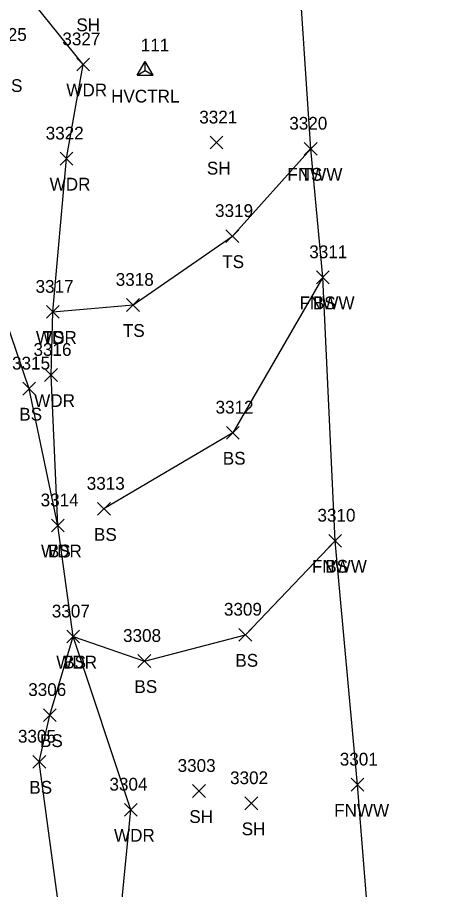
# Model space of a CAD drawing. Extents: x 1650221 to 1650634, y 244606 to 249996.
# Drawn here: x 1650457.2 to 1650522.4, y 246112 to 246248.6 of the extents above; entities that cross this region are included whole.
import ezdxf

# ---------------------------------------------------------------- set-up
doc = ezdxf.new("R2010")
doc.units = 0
for name, color, linetype in [('C_A', 7, 'Continuous'), ('C_I', 7, 'Continuous'), ('CPSM', 7, 'Continuous'), ('L_A', 7, 'Continuous'), ('L_I', 7, 'Continuous'), ('L_TIC', 7, 'Continuous'), ('LAWA', 7, 'Continuous'), ('LELB', 7, 'Continuous'), ('LFNC', 7, 'Continuous'), ('LSOGP', 7, 'Continuous')]:
    doc.layers.add(name, color=color, linetype=linetype)

msp = doc.modelspace()

# ---------------------------------------------------------------- linework, layer by layer
at = {"layer": 'CPSM'}
for p, q in [((1650475.88, 246239.57), (1650477.13, 246241.74)), ((1650478.38, 246239.57), (1650477.13, 246241.74)), ((1650477.13, 246240.29), (1650477.13, 246241.74)), ((1650475.88, 246239.57), (1650477.13, 246240.29)), ((1650477.13, 246240.29), (1650477.13, 246240.29)), ((1650477.13, 246240.29), (1650478.38, 246239.57)), ((1650475.88, 246239.57), (1650478.38, 246239.57))]:
    msp.add_line(p, q, dxfattribs=at)
at = {"layer": 'L_TIC'}
for points in [[(1650466.45, 246240.25), (1650468.45, 246242.25)], [(1650468.45, 246240.25), (1650466.45, 246242.25)], [(1650487.32, 246228.01), (1650489.32, 246230.01)], [(1650489.32, 246228.01), (1650487.32, 246230.01)], [(1650502.06, 246227.04), (1650504.06, 246229.04)], [(1650504.06, 246227.04), (1650502.06, 246229.04)], [(1650502.06, 246227.04), (1650504.06, 246229.04)], [(1650504.06, 246227.04), (1650502.06, 246229.04)], [(1650463.84, 246225.5), (1650465.84, 246227.5)], [(1650465.84, 246225.5), (1650463.84, 246227.5)], [(1650489.8, 246213.36), (1650491.8, 246215.36)], [(1650491.8, 246213.36), (1650489.8, 246215.36)], [(1650503.96, 246206.91), (1650505.96, 246208.91)], [(1650505.96, 246206.91), (1650503.96, 246208.91)], [(1650503.96, 246206.91), (1650505.96, 246208.91)], [(1650505.96, 246206.91), (1650503.96, 246208.91)], [(1650461.69, 246201.49), (1650463.69, 246203.49)], [(1650463.69, 246201.49), (1650461.69, 246203.49)], [(1650461.69, 246201.49), (1650463.69, 246203.49)], [(1650463.69, 246201.49), (1650461.69, 246203.49)], [(1650474.25, 246202.58), (1650476.25, 246204.58)], [(1650476.25, 246202.58), (1650474.25, 246204.58)], [(1650461.42, 246191.61), (1650463.42, 246193.61)], [(1650463.42, 246191.61), (1650461.42, 246193.61)], [(1650458.01, 246189.47), (1650460.01, 246191.47)], [(1650460.01, 246189.47), (1650458.01, 246191.47)], [(1650489.86, 246182.57), (1650491.86, 246184.57)], [(1650491.86, 246182.57), (1650489.86, 246184.57)], [(1650469.7, 246170.64), (1650471.7, 246172.64)], [(1650471.7, 246170.64), (1650469.7, 246172.64)], [(1650462.49, 246168.04), (1650464.49, 246170.04)], [(1650464.49, 246168.04), (1650462.49, 246170.04)], [(1650462.49, 246168.04), (1650464.49, 246170.04)], [(1650464.49, 246168.04), (1650462.49, 246170.04)], [(1650505.9, 246165.65), (1650507.9, 246167.65)], [(1650507.9, 246165.65), (1650505.9, 246167.65)], [(1650505.9, 246165.65), (1650507.9, 246167.65)], [(1650507.9, 246165.65), (1650505.9, 246167.65)], [(1650491.83, 246150.92), (1650493.83, 246152.92)], [(1650493.83, 246150.92), (1650491.83, 246152.92)], [(1650464.87, 246150.64), (1650466.87, 246152.64)], [(1650466.87, 246150.64), (1650464.87, 246152.64)], [(1650464.87, 246150.64), (1650466.87, 246152.64)], [(1650466.87, 246150.64), (1650464.87, 246152.64)], [(1650476.03, 246146.81), (1650478.03, 246148.81)], [(1650478.03, 246146.81), (1650476.03, 246148.81)], [(1650461.24, 246138.34), (1650463.24, 246140.34)], [(1650463.24, 246138.34), (1650461.24, 246140.34)], [(1650459.58, 246131.03), (1650461.58, 246133.03)], [(1650461.58, 246131.03), (1650459.58, 246133.03)], [(1650484.57, 246126.45), (1650486.57, 246128.45)], [(1650486.57, 246126.45), (1650484.57, 246128.45)], [(1650509.38, 246127.44), (1650511.38, 246129.44)], [(1650511.38, 246127.44), (1650509.38, 246129.44)], [(1650473.9, 246123.52), (1650475.9, 246125.52)], [(1650475.9, 246123.52), (1650473.9, 246125.52)], [(1650492.77, 246124.53), (1650494.77, 246126.53)], [(1650494.77, 246124.53), (1650492.77, 246126.53)]]:
    msp.add_lwpolyline(points, dxfattribs=at)
at = {"layer": 'LAWA'}
msp.add_lwpolyline([(1650483.51, 245961.47), (1650475.64, 245986.69), (1650473.95, 246015.71), (1650471, 246044.2), (1650469.07, 246066.54), (1650472.07, 246095.65), (1650474.9, 246124.52), (1650465.87, 246151.64), (1650463.49, 246169.04), (1650462.42, 246192.61), (1650462.69, 246202.49), (1650464.84, 246226.5), (1650467.45, 246241.25), (1650457.44, 246253.74)], dxfattribs=at)
at = {"layer": 'LELB'}
for points in [[(1650463.49, 246169.04), (1650459.01, 246190.47), (1650451.22, 246213.22), (1650448.61, 246231.19), (1650455.93, 246241.94), (1650450.34, 246254.76), (1650459.82, 246278.02), (1650454.44, 246301.53), (1650445.21, 246298.18)], [(1650462.69, 246202.49), (1650475.25, 246203.58), (1650490.8, 246214.36), (1650503.06, 246228.04)], [(1650504.96, 246207.91), (1650490.86, 246183.57), (1650470.7, 246171.64)], [(1650461.78, 246081.8), (1650465.18, 246097.72), (1650460.58, 246132.03), (1650462.24, 246139.34), (1650465.87, 246151.64), (1650477.03, 246147.81), (1650492.83, 246151.92), (1650506.9, 246166.65)]]:
    msp.add_lwpolyline(points, dxfattribs=at)
at = {"layer": 'LFNC'}
msp.add_lwpolyline([(1650522.45, 245965.53), (1650521.47, 245978.98), (1650520.99, 245983.92), (1650520.52, 245992.77), (1650518.16, 246024.52), (1650517.3, 246042.57), (1650515.11, 246068.94), (1650512.39, 246103.56), (1650510.38, 246128.44), (1650506.9, 246166.65), (1650504.96, 246207.91), (1650503.06, 246228.04), (1650500.95, 246260.24)], dxfattribs=at)
at = {"layer": 'LSOGP'}
msp.add_lwpolyline([(1650522.45, 245965.53), (1650521.47, 245978.98), (1650520.99, 245983.92), (1650520.52, 245992.77), (1650518.16, 246024.52), (1650517.3, 246042.57), (1650515.11, 246068.94), (1650512.39, 246103.56), (1650510.38, 246128.44), (1650506.9, 246166.65), (1650504.96, 246207.91), (1650503.06, 246228.04), (1650500.95, 246260.24)], dxfattribs=at)

# ---------------------------------------------------------------- texts
at = {"layer": 'C_A'}
msp.add_text('HVCTRL', height=2, dxfattribs=at).set_placement((1650471.82, 246235.29))
at = {"layer": 'C_I'}
msp.add_text('111', height=2, dxfattribs=at).set_placement((1650476.47, 246243.29))
at = {"layer": 'L_A'}
for s, p in [('SH', (1650466.38, 246246.46)), ('BS', (1650454.37, 246236.94)), ('WDR', (1650464.81, 246236.25)), ('SH', (1650486.81, 246224.01)), ('FNWW', (1650499.41, 246223.04)), ('TS', (1650501.47, 246223.04)), ('WDR', (1650462.2, 246221.5)), ('TS', (1650489.21, 246209.36)), ('FNWW', (1650501.31, 246202.91)), ('BS', (1650503.4, 246202.91)), ('TS', (1650473.66, 246198.58)), ('WDR', (1650460.06, 246197.49)), ('TS', (1650461.1, 246197.49)), ('WDR', (1650459.78, 246187.61)), ('BS', (1650457.45, 246185.47)), ('BS', (1650489.3, 246178.57)), ('BS', (1650469.14, 246166.64)), ('WDR', (1650460.85, 246164.04)), ('BS', (1650461.93, 246164.04)), ('FNWW', (1650503.24, 246161.65)), ('BS', (1650505.34, 246161.65)), ('BS', (1650491.27, 246146.92)), ('WDR', (1650463.24, 246146.64)), ('BS', (1650464.32, 246146.64)), ('BS', (1650475.47, 246142.81)), ('BS', (1650460.69, 246134.34)), ('BS', (1650459.02, 246127.03)), ('SH', (1650484.06, 246122.45)), ('FNWW', (1650506.73, 246123.44)), ('WDR', (1650472.27, 246119.52)), ('SH', (1650492.26, 246120.53))]:
    msp.add_text(s, height=2, dxfattribs=at).set_placement(p)
at = {"layer": 'L_I'}
for s, p in [('3325', (1650452.67, 246244.94)), ('3327', (1650464.19, 246244.25)), ('3321', (1650485.62, 246232.01)), ('3320', (1650499.71, 246231.04)), ('3320', (1650499.71, 246231.04)), ('3322', (1650461.58, 246229.5)), ('3319', (1650488.09, 246217.36)), ('3311', (1650502.84, 246210.91)), ('3311', (1650502.84, 246210.91)), ('3317', (1650460, 246205.49)), ('3317', (1650460, 246205.49)), ('3318', (1650472.55, 246206.58)), ('3316', (1650459.67, 246195.61)), ('3315', (1650456.32, 246193.47)), ('3312', (1650488.17, 246186.57)), ('3313', (1650468.01, 246174.64)), ('3314', (1650460.79, 246172.04)), ('3314', (1650460.79, 246172.04)), ('3310', (1650504.12, 246169.65)), ('3310', (1650504.12, 246169.65)), ('3309', (1650489.48, 246154.92)), ('3307', (1650462.54, 246154.64)), ('3307', (1650462.54, 246154.64)), ('3308', (1650473.69, 246150.81)), ('3306', (1650458.85, 246142.34)), ('3305', (1650457.24, 246135.03)), ('3303', (1650482.23, 246130.45)), ('3301', (1650507.61, 246131.44)), ('3302', (1650490.44, 246128.53)), ('3304', (1650471.56, 246127.52))]:
    msp.add_text(s, height=2, dxfattribs=at).set_placement(p)

doc.saveas('drawing.dxf')
